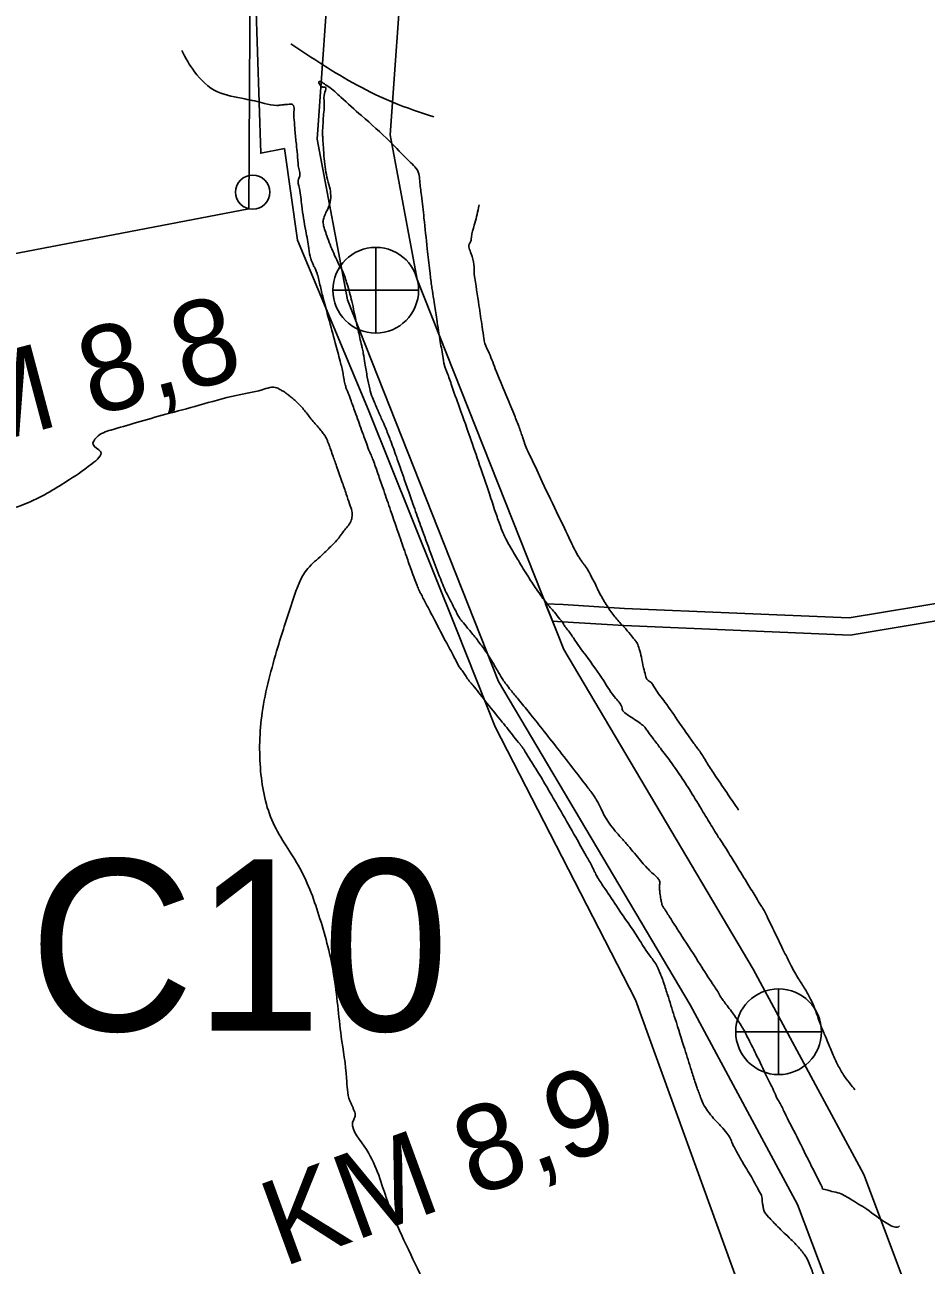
# Model space of a CAD drawing. Extents: x -478232 to -472707, y -1118753 to -1113967.
# Drawn here: x -476275.2 to -476170, y -1117016.9 to -1116872.1 of the extents above; entities that cross this region are included whole.
import ezdxf

# ---------------------------------------------------------------- set-up
doc = ezdxf.new("R2010")
doc.units = 0
for name, color, linetype in [('cesty', 7, 'Continuous'), ('ObPÚ', 7, 'Continuous'), ('staničení toku', 7, 'Continuous'), ('vodní plochy', 7, 'Continuous'), ('Vrstevnice_vedlejsi', 7, 'Continuous')]:
    doc.layers.add(name, color=color, linetype=linetype)

msp = doc.modelspace()

# ---------------------------------------------------------------- linework, layer by layer
at = {"layer": 'cesty'}
msp.add_circle((-476248.596, -1116891.652), 2, dxfattribs=at)
at = {"layer": 'ObPÚ'}
msp.add_lwpolyline([(-476231.32, -1117146.23), (-476236.27, -1117130.89), (-476247.01, -1117093.59), (-476239.42, -1117084.68), (-476211.73, -1117075.38), (-476202.62, -1117071.28), (-476198.91, -1117063.87), (-476198.91, -1117063.87), (-476189.59, -1117026.33), (-476192, -1117018.92), (-476203.93, -1116985.93), (-476220.32, -1116954.06), (-476224.82, -1116942.7), (-476235.08, -1116917.09), (-476243.37, -1116897.27), (-476244.9, -1116886.57), (-476247.65, -1116887.11), (-476248.8, -1116851.56), (-476249.04, -1116893.61), (-476326.63, -1116908.47), (-476339.71, -1116869.87), (-476350.95, -1116836.63), (-476357.4, -1116837.74), (-476422.93, -1116845.91)], dxfattribs=at)
at = {"layer": 'staničení toku'}
for p, q in [((-476234.237, -1116898.091), (-476234.237, -1116908.091)), ((-476229.237, -1116903.091), (-476239.237, -1116903.091)), ((-476187.225, -1116984.636), (-476187.225, -1116994.636)), ((-476182.225, -1116989.636), (-476192.225, -1116989.636))]:
    msp.add_line(p, q, dxfattribs=at)
for centre in [(-476234.237, -1116903.091), (-476187.225, -1116989.636)]:
    msp.add_circle(centre, 5, dxfattribs=at)
at = {"layer": 'vodní plochy'}
for points in [[(-476226.591, -1116759.508), (-476233.031, -1116820.563), (-476234.839, -1116830.738), (-476239.473, -1116862.842), (-476241.054, -1116885.449), (-476237.552, -1116904.211), (-476219.926, -1116948.75), (-476197.554, -1116986.509), (-476185.01, -1117009.8), (-476178.454, -1117027.217), (-476175.516, -1117055.259), (-476169.64, -1117101.16), (-476164.216, -1117139.146), (-476155.629, -1117189.113), (-476151.336, -1117200.415), (-476144.105, -1117217.145), (-476127.944, -1117246.546), (-476126.587, -1117261.477), (-476126.248, -1117271.88), (-476127.83, -1117290.877), (-476130.77, -1117309.424), (-476146.817, -1117341.989), (-476156.309, -1117361.66)], [(-476148.691, -1117365.336), (-476139.214, -1117345.696), (-476122.616, -1117312.014), (-476119.427, -1117291.891), (-476117.778, -1117272.094), (-476118.141, -1117260.956), (-476119.68, -1117244.02), (-476136.499, -1117213.422), (-476143.496, -1117197.234), (-476147.431, -1117186.874), (-476155.859, -1117137.831), (-476161.257, -1117100.025), (-476167.113, -1117054.281), (-476170.155, -1117025.255), (-476177.294, -1117006.289), (-476190.188, -1116982.346), (-476212.307, -1116945.014), (-476229.386, -1116901.857), (-476232.54, -1116884.96), (-476231.056, -1116863.743), (-476226.487, -1116832.083), (-476224.65, -1116821.748), (-476218.166, -1116760.281)], [(-476055.697, -1116942.457), (-476063.109, -1116938.121), (-476082.268, -1116931.129), (-476102.796, -1116929.035), (-476121.999, -1116929.452), (-476138.271, -1116931.26), (-476145.701, -1116932.661), (-476166.725, -1116939.301), (-476179.006, -1116941.348), (-476205.195, -1116940.233), (-476212.357, -1116939.782), (-476214.41, -1116939.701)], [(-476178.882, -1116943.356), (-476166.257, -1116941.251), (-476145.213, -1116934.605), (-476137.975, -1116933.24), (-476121.867, -1116931.45), (-476102.876, -1116931.037), (-476082.72, -1116933.093), (-476063.963, -1116939.939), (-476056.707, -1116944.183)], [(-476214.41, -1116939.701), (-476213.605, -1116941.734)], [(-476213.605, -1116941.734), (-476212.459, -1116941.78)], [(-476212.459, -1116941.78), (-476205.301, -1116942.231), (-476178.882, -1116943.356)]]:
    msp.add_lwpolyline(points, dxfattribs=at)
at = {"layer": 'Vrstevnice_vedlejsi'}
for points in [[(-476244.145, -1116874.347), (-476240.419, -1116876.782), (-476232.182, -1116881.186), (-476227.467, -1116882.859)], [(-476219.474, -1116953.504), (-476221.507, -1116950.97), (-476222.911, -1116949.198), (-476223.686, -1116948.188), (-476223.832, -1116947.94), (-476223.992, -1116947.699), (-476224.165, -1116947.465), (-476224.351, -1116947.24), (-476224.949, -1116946.183), (-476225.958, -1116944.295), (-476227.379, -1116941.576), (-476228.39, -1116939.641), (-476228.99, -1116938.489), (-476229.178, -1116938.121), (-476229.422, -1116937.55), (-476229.72, -1116936.777), (-476230.073, -1116935.801), (-476230.654, -1116934.147), (-476231.463, -1116931.813), (-476232.499, -1116928.8), (-476233.31, -1116926.448), (-476233.894, -1116924.756), (-476234.253, -1116923.725), (-476234.552, -1116922.906), (-476234.789, -1116922.301), (-476234.964, -1116921.909), (-476235.332, -1116920.947), (-476235.892, -1116919.415), (-476236.643, -1116917.314), (-476237.19, -1116915.806), (-476237.534, -1116914.891), (-476237.673, -1116914.569), (-476237.806, -1116914.117), (-476237.932, -1116913.534), (-476238.05, -1116912.822), (-476238.391, -1116911.388), (-476238.954, -1116909.232), (-476239.74, -1116906.355), (-476240.322, -1116904.17), (-476240.701, -1116902.675), (-476240.877, -1116901.872), (-476241.053, -1116901.226), (-476241.227, -1116900.738), (-476241.401, -1116900.408), (-476241.556, -1116900.079), (-476241.692, -1116899.75), (-476241.81, -1116899.423), (-476242.045, -1116898.228), (-476242.399, -1116896.166), (-476242.871, -1116893.237), (-476243.15, -1116891.211), (-476243.238, -1116890.088), (-476243.132, -1116889.867), (-476243.089, -1116889.622), (-476243.107, -1116889.352), (-476243.188, -1116889.058), (-476243.249, -1116888.741), (-476243.292, -1116888.401), (-476243.317, -1116888.039), (-476243.386, -1116887.259), (-476243.502, -1116886.062), (-476243.662, -1116884.447), (-476243.76, -1116883.207), (-476243.794, -1116882.34), (-476243.766, -1116881.846), (-476243.848, -1116881.524), (-476244.042, -1116881.373), (-476244.348, -1116881.394), (-476244.738, -1116881.426), (-476245.212, -1116881.47), (-476245.772, -1116881.526), (-476247.205, -1116881.289), (-476249.512, -1116880.759), (-476252.692, -1116879.936), (-476255.384, -1116877.596), (-476256.88, -1116875.123)], [(-476240.268, -1116879.409), (-476240.571, -1116879.33), (-476240.699, -1116879.219), (-476240.804, -1116879.035), (-476240.886, -1116878.779), (-476240.744, -1116878.74), (-476240.38, -1116878.917), (-476239.793, -1116879.31), (-476238.3, -1116880.576), (-476235.902, -1116882.716), (-476232.598, -1116885.728), (-476230.363, -1116887.998), (-476229.197, -1116889.525), (-476229.099, -1116890.308), (-476228.903, -1116892.024), (-476228.609, -1116894.673), (-476228.217, -1116898.254), (-476227.921, -1116900.864), (-476227.723, -1116902.503), (-476227.622, -1116903.17), (-476227.419, -1116904.496), (-476227.114, -1116906.481), (-476226.707, -1116909.124), (-476226.383, -1116911.013), (-476226.142, -1116912.15), (-476225.984, -1116912.532), (-476225.425, -1116914.075), (-476224.466, -1116916.776), (-476223.107, -1116920.638), (-476221.969, -1116923.915), (-476221.054, -1116926.606), (-476220.361, -1116928.714), (-476219.798, -1116930.332), (-476219.365, -1116931.461), (-476219.061, -1116932.102), (-476218.47, -1116933.165), (-476217.593, -1116934.649), (-476216.43, -1116936.555), (-476215.343, -1116938.196), (-476214.331, -1116939.569), (-476213.396, -1116940.677), (-476212.742, -1116941.478), (-476212.368, -1116941.971), (-476212.274, -1116942.158), (-476212.174, -1116942.325), (-476212.066, -1116942.472), (-476211.951, -1116942.6), (-476211.175, -1116943.679), (-476209.736, -1116945.707), (-476207.637, -1116948.685), (-476206.223, -1116950.743), (-476205.494, -1116951.883), (-476205.452, -1116952.103), (-476205.161, -1116952.412), (-476204.621, -1116952.812), (-476203.833, -1116953.302), (-476203.209, -1116953.77), (-476202.749, -1116954.216), (-476202.454, -1116954.641), (-476201.876, -1116955.421), (-476201.016, -1116956.558), (-476199.873, -1116958.049), (-476198.637, -1116959.829), (-476197.307, -1116961.897), (-476195.883, -1116964.253), (-476194.826, -1116965.982), (-476194.136, -1116967.085), (-476193.813, -1116967.561), (-476193.151, -1116968.609), (-476192.15, -1116970.229), (-476190.81, -1116972.421), (-476189.849, -1116973.989), (-476189.265, -1116974.93), (-476189.059, -1116975.247), (-476188.566, -1116976.205), (-476187.785, -1116977.804), (-476186.717, -1116980.044), (-476185.754, -1116981.933), (-476184.895, -1116983.47), (-476184.141, -1116984.656), (-476183.507, -1116985.819), (-476182.993, -1116986.959), (-476182.599, -1116988.076), (-476182.306, -1116988.884), (-476182.116, -1116989.383), (-476182.029, -1116989.572), (-476181.765, -1116990.192), (-476181.323, -1116991.242), (-476180.705, -1116992.723), (-476180.044, -1116994.021), (-476179.341, -1116995.138), (-476178.594, -1116996.072), (-476178.337, -1116996.4)], [(-476233.098, -1116919.126), (-476233.516, -1116918.195), (-476233.8, -1116917.557), (-476233.952, -1116917.21), (-476233.972, -1116917.156), (-476234.091, -1116916.874), (-476234.311, -1116916.364), (-476234.631, -1116915.627), (-476234.935, -1116914.592), (-476235.222, -1116913.258), (-476235.494, -1116911.627), (-476235.693, -1116910.474), (-476235.819, -1116909.799), (-476235.873, -1116909.602), (-476236.092, -1116908.635), (-476236.477, -1116906.897), (-476237.027, -1116904.388), (-476237.574, -1116902.372), (-476238.119, -1116900.847), (-476238.662, -1116899.816), (-476239.146, -1116898.787), (-476239.571, -1116897.761), (-476239.938, -1116896.738), (-476240.198, -1116895.961), (-476240.351, -1116895.429), (-476240.397, -1116895.142), (-476240.297, -1116894.677), (-476240.05, -1116894.032), (-476239.657, -1116893.208), (-476239.495, -1116892.294), (-476239.564, -1116891.287), (-476239.865, -1116890.19), (-476240.095, -1116889.007), (-476240.255, -1116887.739), (-476240.346, -1116886.384), (-476240.409, -1116885.456), (-476240.444, -1116884.953), (-476240.452, -1116884.877), (-476240.422, -1116884.225), (-476240.354, -1116882.999), (-476240.249, -1116881.198), (-476240.184, -1116879.998), (-476240.159, -1116879.399), (-476240.174, -1116879.4), (-476240.192, -1116879.401), (-476240.215, -1116879.403), (-476240.268, -1116879.409)], [(-476222.172, -1116893.14), (-476222.238, -1116893.464), (-476222.736, -1116895.514), (-476223.074, -1116896.889), (-476223.252, -1116897.588), (-476223.272, -1116897.612), (-476223.102, -1116898.834), (-476222.743, -1116901.254)], [(-476222.743, -1116901.254), (-476222.194, -1116904.871), (-476221.815, -1116907.368), (-476221.607, -1116908.743), (-476221.567, -1116908.997), (-476221.127, -1116910.168), (-476220.285, -1116912.256), (-476219.042, -1116915.26), (-476218.133, -1116917.49), (-476217.559, -1116918.947), (-476217.319, -1116919.629), (-476217.118, -1116920.207), (-476216.956, -1116920.683), (-476216.834, -1116921.055), (-476216.116, -1116922.643), (-476214.803, -1116925.448), (-476212.894, -1116929.47), (-476211.532, -1116932.297), (-476210.717, -1116933.932), (-476210.448, -1116934.373), (-476210.196, -1116934.752), (-476209.962, -1116935.07), (-476209.746, -1116935.327), (-476209.341, -1116936.018), (-476208.749, -1116937.145), (-476207.968, -1116938.708), (-476207.126, -1116940.108), (-476206.223, -1116941.344), (-476205.26, -1116942.418), (-476204.526, -1116943.264), (-476204.022, -1116943.881), (-476203.748, -1116944.269), (-476203.485, -1116944.949), (-476203.231, -1116945.919), (-476202.988, -1116947.181), (-476202.756, -1116948.066), (-476202.534, -1116948.574), (-476202.323, -1116948.705), (-476201.64, -1116949.572), (-476200.485, -1116951.175), (-476198.858, -1116953.514), (-476197.67, -1116955.21), (-476196.919, -1116956.261), (-476196.607, -1116956.67), (-476196.269, -1116957.156), (-476195.905, -1116957.722), (-476195.515, -1116958.366), (-476194.58, -1116959.792), (-476193.098, -1116961.998), (-476191.888, -1116963.78)], [(-476316.243, -1116908.48), (-476314.561, -1116908.998), (-476313.123, -1116909.665), (-476311.928, -1116910.479), (-476310.975, -1116911.441), (-476307.447, -1116912.926), (-476301.342, -1116914.935), (-476292.661, -1116917.468), (-476286.431, -1116920.344), (-476282.653, -1116923.565), (-476281.326, -1116927.13), (-476278.825, -1116928.622), (-476275.148, -1116928.043), (-476270.296, -1116925.391), (-476267.359, -1116923.353), (-476266.337, -1116921.926), (-476267.229, -1116921.113), (-476266.831, -1116920.277), (-476265.141, -1116919.419), (-476262.159, -1116918.539), (-476258.731, -1116917.573), (-476254.857, -1116916.522), (-476250.536, -1116915.385), (-476247.506, -1116914.708), (-476245.767, -1116914.49), (-476245.318, -1116914.73), (-476244.967, -1116914.931), (-476244.714, -1116915.09), (-476244.558, -1116915.209), (-476244.297, -1116915.426), (-476243.929, -1116915.74), (-476243.455, -1116916.152), (-476242.992, -1116916.618), (-476242.539, -1116917.137), (-476242.097, -1116917.711), (-476241.648, -1116918.268), (-476241.19, -1116918.809), (-476240.724, -1116919.335), (-476240.357, -1116919.802), (-476240.09, -1116920.212), (-476239.921, -1116920.565), (-476239.776, -1116920.901), (-476239.653, -1116921.22), (-476239.554, -1116921.522), (-476239.275, -1116922.323), (-476238.817, -1116923.622), (-476238.18, -1116925.419), (-476237.671, -1116926.892), (-476237.289, -1116928.04), (-476237.035, -1116928.865), (-476237.012, -1116929.601), (-476237.222, -1116930.251), (-476237.665, -1116930.812), (-476238.042, -1116931.305), (-476238.354, -1116931.728), (-476238.601, -1116932.083), (-476239.32, -1116932.842), (-476240.511, -1116934.008), (-476242.173, -1116935.579), (-476243.89, -1116939.165), (-476245.66, -1116944.767), (-476247.485, -1116952.383), (-476247.667, -1116959.217), (-476246.206, -1116965.267), (-476243.103, -1116970.535), (-476240.745, -1116976.442), (-476239.133, -1116982.988), (-476238.266, -1116990.175), (-476237.639, -1116995.076), (-476237.25, -1116997.694), (-476237.099, -1116998.028), (-476236.956, -1116998.362), (-476236.818, -1116998.698), (-476236.687, -1116999.033), (-476236.643, -1116999.341), (-476236.684, -1116999.621), (-476236.813, -1116999.873), (-476235.592, -1117002.993), (-476233.023, -1117008.983), (-476229.104, -1117017.842), (-476226.381, -1117023.996), (-476224.854, -1117027.447), (-476224.521, -1117028.193), (-476224.304, -1117028.701), (-476224.204, -1117028.973), (-476224.22, -1117029.007), (-476224.213, -1117029.062), (-476224.183, -1117029.137), (-476224.131, -1117029.234), (-476224.075, -1117029.288), (-476224.014, -1117029.297), (-476223.948, -1117029.262), (-476223.307, -1117029.574), (-476222.09, -1117030.231), (-476220.296, -1117031.233), (-476219.154, -1117032.301), (-476218.662, -1117033.435)], [(-476173.103, -1117012.293), (-476173.113, -1117012.305), (-476174.489, -1117012.063), (-476176.945, -1117010.357), (-476178.885, -1117009.146), (-476180.309, -1117008.431), (-476181.215, -1117008.21), (-476181.823, -1117008.04), (-476182.131, -1117007.921), (-476182.141, -1117007.853), (-476182.149, -1117007.804), (-476182.156, -1117007.774), (-476182.161, -1117007.763), (-476182.717, -1117006.652), (-476183.826, -1117004.442), (-476185.486, -1117001.132), (-476186.609, -1116998.901), (-476187.196, -1116997.749), (-476187.245, -1116997.676), (-476187.707, -1116996.731), (-476188.583, -1116994.914), (-476189.873, -1116992.225), (-476190.878, -1116990.218), (-476191.598, -1116988.894), (-476192.033, -1116988.252), (-476192.495, -1116987.598), (-476192.984, -1116986.93), (-476193.499, -1116986.249), (-476193.867, -1116985.746), (-476194.088, -1116985.419), (-476194.161, -1116985.27), (-476194.922, -1116984.065), (-476196.371, -1116981.802), (-476198.508, -1116978.483), (-476199.956, -1116976.235), (-476200.715, -1116975.057), (-476200.784, -1116974.951), (-476200.866, -1116974.652), (-476200.961, -1116974.161), (-476201.068, -1116973.479), (-476201.125, -1116972.927), (-476201.131, -1116972.506), (-476201.087, -1116972.215), (-476201.217, -1116971.883), (-476201.522, -1116971.509), (-476202.002, -1116971.092), (-476202.55, -1116970.54), (-476203.168, -1116969.851), (-476203.855, -1116969.027), (-476204.605, -1116968.145), (-476205.415, -1116967.207), (-476206.288, -1116966.213), (-476206.999, -1116965.285), (-476207.547, -1116964.423), (-476207.932, -1116963.627), (-476208.259, -1116962.985), (-476208.527, -1116962.496), (-476208.735, -1116962.161), (-476209.555, -1116961.061), (-476210.986, -1116959.198), (-476213.028, -1116956.571), (-476214.81, -1116954.304), (-476216.333, -1116952.396), (-476217.596, -1116950.847), (-476218.484, -1116949.757), (-476218.998, -1116949.125), (-476219.137, -1116948.951), (-476219.484, -1116948.403), (-476220.04, -1116947.481), (-476220.803, -1116946.183), (-476221.636, -1116944.926), (-476222.538, -1116943.708), (-476223.511, -1116942.529), (-476224.181, -1116941.701), (-476224.55, -1116941.222), (-476224.618, -1116941.092), (-476224.867, -1116940.609), (-476225.297, -1116939.772), (-476225.908, -1116938.581), (-476226.696, -1116936.735), (-476227.661, -1116934.234), (-476228.803, -1116931.078), (-476229.584, -1116928.916), (-476230.005, -1116927.748), (-476230.065, -1116927.573), (-476230.389, -1116926.641), (-476230.977, -1116924.952), (-476231.829, -1116922.504), (-476232.536, -1116920.562), (-476233.098, -1116919.126)], [(-476179.724, -1117035.627), (-476179.75, -1117035.303), (-476179.782, -1117035.021), (-476179.82, -1117034.78), (-476179.865, -1117034.582), (-476179.89, -1117034.419), (-476179.894, -1117034.292), (-476179.878, -1117034.199), (-476179.879, -1117034.093), (-476179.896, -1117033.973), (-476179.929, -1117033.839), (-476180.135, -1117032.979), (-476180.515, -1117031.393), (-476181.068, -1117029.081), (-476181.748, -1117027.028), (-476182.554, -1117025.234), (-476183.488, -1117023.699), (-476184.151, -1117022.618), (-476184.543, -1117021.993), (-476184.665, -1117021.823), (-476184.551, -1117021.459), (-476184.202, -1117020.899), (-476183.616, -1117020.145), (-476183.252, -1117019.523), (-476183.11, -1117019.034), (-476183.19, -1117018.678), (-476183.244, -1117018.432), (-476183.271, -1117018.296), (-476183.272, -1117018.269), (-476183.261, -1117018.232), (-476183.237, -1117018.185), (-476183.201, -1117018.126), (-476183.188, -1117018.039), (-476183.199, -1117017.923), (-476183.234, -1117017.779), (-476183.365, -1117017.428), (-476183.592, -1117016.87), (-476183.916, -1117016.106), (-476184.647, -1117015.105), (-476185.785, -1117013.867), (-476187.33, -1117012.392), (-476188.388, -1117011.262), (-476188.958, -1117010.478), (-476189.041, -1117010.039), (-476189.106, -1117009.636), (-476189.153, -1117009.267), (-476189.182, -1117008.935), (-476189.557, -1117008.114), (-476190.278, -1117006.805), (-476191.346, -1117005.008), (-476192.127, -1117003.633), (-476192.621, -1117002.68), (-476192.828, -1117002.148), (-476193.262, -1117001.482), (-476193.923, -1117000.684), (-476194.811, -1116999.752), (-476195.507, -1116998.877), (-476196.011, -1116998.058), (-476196.323, -1116997.295), (-476196.58, -1116996.639), (-476196.782, -1116996.088), (-476196.93, -1116995.644), (-476197.398, -1116994.17), (-476198.187, -1116991.667), (-476199.296, -1116988.134), (-476200.094, -1116985.612), (-476200.58, -1116984.1), (-476200.756, -1116983.599), (-476200.905, -1116983.191), (-476201.028, -1116982.876), (-476201.124, -1116982.653), (-476201.204, -1116982.463), (-476201.268, -1116982.305), (-476201.315, -1116982.181), (-476202.111, -1116980.963), (-476203.654, -1116978.651), (-476205.945, -1116975.246), (-476207.511, -1116972.904), (-476208.351, -1116971.625), (-476208.466, -1116971.41), (-476208.609, -1116971.129), (-476208.78, -1116970.784), (-476208.979, -1116970.373), (-476209.684, -1116969.095), (-476210.895, -1116966.948), (-476212.612, -1116963.934), (-476214.062, -1116961.433), (-476215.245, -1116959.445), (-476216.162, -1116957.97), (-476216.798, -1116956.955), (-476217.154, -1116956.399), (-476217.228, -1116956.303), (-476217.294, -1116956.22), (-476217.349, -1116956.15), (-476217.396, -1116956.094), (-476218.104, -1116955.211), (-476219.474, -1116953.504)]]:
    msp.add_spline(points, degree=3, dxfattribs=at)

# ---------------------------------------------------------------- texts
at = {"layer": 'cesty'}
msp.add_text('C10', height=20, rotation=359.99999, dxfattribs=at).set_placement((-476274.717, -1116989.523))
at = {"layer": 'staničení toku'}
for s, rotation, p in [('KM 8,8', 14.877, (-476290.291, -1116923.945)), ('KM 8,9', 20.07661, (-476245.087, -1117017.136))]:
    msp.add_text(s, height=10, rotation=rotation, dxfattribs=at).set_placement(p)

doc.saveas('drawing.dxf')
